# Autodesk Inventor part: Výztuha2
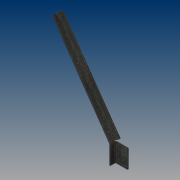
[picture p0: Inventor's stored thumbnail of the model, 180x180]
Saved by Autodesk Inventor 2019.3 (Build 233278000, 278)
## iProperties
Created: 2019-02
Part Number: Výztuha2
Material: Ocel, měkká, svařovaná
Document SubType Name: Plech
Designer: B-hon
Density: 7.85 g/cm^3
Sheet Metal Rule: Výchozí_mm
Appearance: Plech
Author: B-hon
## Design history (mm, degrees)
node "Plocha1"
  sketch "Náčrt1"
    geometry: L1 (-7, 0)-(-48, 0); L2 (-48, 0)-(-48, 390); L3 (-7, 390)-(-7, 0); L4 (-48, 390)-(-7, 390); 5 further points
    constraints: 8 end point, 2 horizontal alignment, 1 horizontal, 1 parallel, 1 perpendicular
    dimensions: "d5" = 7 vertical distance of point (0, 0) point (-17, 7); "d6" = 17 horizontal distance of point (0, 0) point (-17, 7); "d7" = 21 distance of point (-38, 7) point (-17, 7); "d8" = 45 vertical distance of point (-17, 7) point (-27.5, 52); "d9" = 10.5 horizontal distance of point (-17, 7) point (-27.5, 52) (= 0.5 x d7); "d10" = 10 distance from line of point (-17, 7) L3; "d11" = 10 distance from line of point (-38, 7) L2 (= d10); "d12" = 250 distance from line of L3 point (243, 370); "d13" = 370 distance from line of L1 point (243, 370); "d15" = 390 distance of L1.end L2.end
node "Obruba4"
sketch "Náčrt9"
  geometry: L1 (14, 0)-(14, 390) reference; L2 (29.659, 62)-(14, 62); L3 (14, 62)-(14, 60); L4 (14, 60)-(29.659, 60); L5 (29.659, 60)-(29.659, 62); L6 (17, 0)-(14, 0) reference; 1 further point
  constraints: 8 end point, 2 parallel, 1 horizontal, 1 perpendicular, 1 point on line
  dimensions: "d83" = 2 distance of L4.end L2.start; "d84" = 60 distance between parallel lines of L6 L4
extrude "Vysunutí2" cut sketch "Náčrt9" stored distance "d85" = 200; taper "d86" = 0 deg
sketch "Náčrt10"
  geometry: L1 (-67.25, 60)-(25.208, 60); L2 (-20, 60)-(-14, 60) reference; 1 further point
  constraints: 2 end point, 1 collinear
  dimensions: "d87" = 0 distance between parallel lines of L1 L2
feature "Ohyb součásti2" sketch "Náčrt10" dims "d88" = 3, "d89" = 35 deg
node "Upravit přímo2"
sketch "Náčrt11"
  geometry: L1 (48, 60)-(48, 0) reference; L2 (7, 0)-(42, 0) reference; 4 further points
  constraints: 1 horizontal alignment
  dimensions: "d93" = 14 distance from line of point (34, 7) L1; "d94" = 7 distance from line of L2 point (34, 7); "d95" = 21 distance of point (34, 7) point (13, 7); "d96" = 45 vertical distance of point (34, 7) point (23.5, 52); "d97" = 10.5 horizontal distance of point (34, 7) point (23.5, 52) (= 0.5 x d95)
hole "Díra2" sketch "Náčrt11" at (34, 7), (13, 7), (23.5, 52) diameter "d98" = 5.5; stored, may be unused: countersink angle "d102" = 90 deg, drill point angle "d104" = 0 deg; dims "d99" = 6, "d100" = 4, "d101" = 2, "d103" = 3 (= Tloušťka)
node "Upravit přímo3"
node "Těleso1"
feature "Deska1" dims "d14" = 3 (= Tloušťka)
sketch "Náčrt8"
  geometry: L1 through (-195, 0) direction (1, 1.12e-48); L2 through (0, 10) direction (1.23e-32, 1); L3 (0, 20)-(-390, 20); L4 (-390, 20)-(-390, 0)
  constraints: 6 end point, 1 horizontal, 1 perpendicular, 1 vertical
feature "Deska5" dims "d14" = 3 (= Tloušťka), "d73" = 3 (= ŠířkaVýštipu), "d74" = 1.5 (= HloubkaVýštipu), "d75" = 6 (= MinimálníZbytek), "d76" = 3 (= PřechodovýPoloměr), "d77" = 20, "d78" = 90 deg, "d79" = 3 (= PoloměrOhybu), "d80" = 12 (= VelikostRohovéhoVýštipu), "d81" = 3 (= VelikostMezery), "d82" = 3 (= VelikostJacobihoPoloměru), "MezeraVystřižení" = 0.01
feature "Ohyb4" dims "d14" = 3 (= Tloušťka), "d73" = 3 (= ŠířkaVýštipu), "d74" = 1.5 (= HloubkaVýštipu), "d75" = 6 (= MinimálníZbytek), "d76" = 3 (= PřechodovýPoloměr), "d77" = 20, "d78" = 90 deg, "d79" = 3 (= PoloměrOhybu), "MezeraVystřižení" = 0.01
feature "Roh4" dims "d77" = 20, "d78" = 90 deg, "d80" = 12 (= VelikostRohovéhoVýštipu), "d81" = 3 (= VelikostMezery), "d82" = 3 (= VelikostJacobihoPoloměru)
feature "Posunout2" dims "d92" = -20
feature "Posunout3" dims "d107" = 1
other parameters: "Tloušťka" = 3 (derived), "KSoučinitel" = 4.4, "PoloměrOhybu" = 3 (= Tloušťka), "ŠířkaVýštipu" = 3 (= Tloušťka), "HloubkaVýštipu" = 1.5 (= 0.5 x Tloušťka), "VelikostRohovéhoVýštipu" = 12 (= 4 x Tloušťka), "MinimálníZbytek" = 6 (= 2 x Tloušťka), "PřechodovýPoloměr" = 3 (= PoloměrOhybu), "VelikostJacobihoPoloměru" = 3 (= PoloměrOhybu), "VelikostMezery" = 3 (= Tloušťka), "d90" = 0, "d91" = 0, "d105" = 0, "d106" = 0
